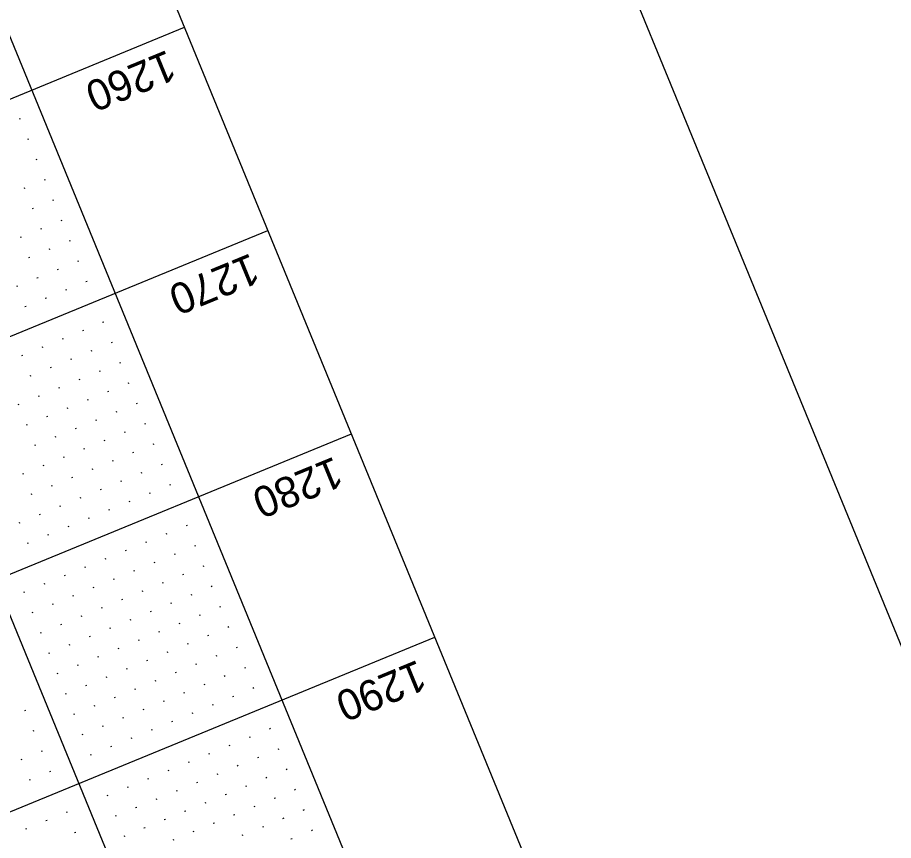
# Model space of a CAD drawing. Extents: x 2148770 to 2150891, y 142633 to 144465.
# Drawn here: x 2150307.4 to 2150506.7, y 143987.8 to 144175 of the extents above; entities that cross this region are included whole.
import ezdxf

# ---------------------------------------------------------------- set-up
doc = ezdxf.new("R2010")
doc.units = 0
for name, color, linetype in [('SHT_Plan_Profile_Sheet_Elev_Txt', 7, 'Continuous'), ('SHT_Plot_Shape_Half', 7, 'Continuous'), ('SHT_Profile_Grid_Major', 7, 'Continuous'), ('SHT_Profile_Grid_Minor', 7, 'Continuous'), ('SHT_Sheet_Border', 7, 'Continuous')]:
    doc.layers.add(name, color=color, linetype=linetype)

msp = doc.modelspace()

# ---------------------------------------------------------------- linework, layer by layer
at = {"layer": 'SHT_Plot_Shape_Half'}
msp.add_lwpolyline([(2150799.14, 143324.02), (2149226.52, 142678.36), (2148808.74, 143695.93), (2150381.36, 144341.59)], close=True, dxfattribs=at)
at = {"layer": 'SHT_Profile_Grid_Major'}
for p, q in [((2150226.36, 144232.01), (2150416.26, 143769.48)), ((2150345.29, 144172.74), (2148888.3, 143574.55)), ((2150364.28, 144126.48), (2148907.29, 143528.3)), ((2150383.27, 144080.23), (2148926.28, 143482.05)), ((2150402.26, 144033.98), (2148945.27, 143435.79))]:
    msp.add_line(p, q, dxfattribs=at)
at = {"layer": 'SHT_Profile_Grid_Minor'}
for p, q in [((2150307.98, 144152.02), (2150307.75, 144151.92)), ((2150309.88, 144147.39), (2150309.65, 144147.3)), ((2150311.78, 144142.77), (2150311.55, 144142.67)), ((2150313.68, 144138.14), (2150313.45, 144138.05)), ((2150309.06, 144136.24), (2150308.82, 144136.15)), ((2150315.58, 144133.52), (2150315.35, 144133.42)), ((2150310.96, 144131.62), (2150310.72, 144131.52)), ((2150317.48, 144128.89), (2150317.25, 144128.8)), ((2150312.85, 144126.99), (2150312.62, 144126.9)), ((2150308.23, 144125.09), (2150308, 144125)), ((2150319.38, 144124.27), (2150319.15, 144124.17)), ((2150314.75, 144122.37), (2150314.52, 144122.27)), ((2150310.13, 144120.47), (2150309.9, 144120.37)), ((2150321.28, 144119.64), (2150321.05, 144119.55)), ((2150316.65, 144117.74), (2150316.42, 144117.65)), ((2150312.03, 144115.84), (2150311.8, 144115.75)), ((2150323.18, 144115.02), (2150322.95, 144114.92)), ((2150307.4, 144113.94), (2150307.17, 144113.85)), ((2150318.55, 144113.12), (2150318.32, 144113.02)), ((2150313.93, 144111.22), (2150313.69, 144111.12)), ((2150309.3, 144109.32), (2150309.07, 144109.22)), ((2150326.97, 144105.77), (2150326.74, 144105.67)), ((2150322.35, 144103.87), (2150322.12, 144103.77)), ((2150317.72, 144101.97), (2150317.49, 144101.87)), ((2150328.87, 144101.14), (2150328.64, 144101.05)), ((2150313.1, 144100.07), (2150312.87, 144099.97)), ((2150324.25, 144099.24), (2150324.02, 144099.15)), ((2150308.47, 144098.17), (2150308.24, 144098.07)), ((2150319.62, 144097.34), (2150319.39, 144097.25)), ((2150315, 144095.44), (2150314.77, 144095.35)), ((2150330.77, 144096.51), (2150330.54, 144096.42)), ((2150310.37, 144093.54), (2150310.14, 144093.45)), ((2150326.15, 144094.62), (2150325.92, 144094.52)), ((2150321.52, 144092.72), (2150321.29, 144092.62)), ((2150332.67, 144091.89), (2150332.44, 144091.79)), ((2150316.9, 144090.82), (2150316.67, 144090.72)), ((2150328.05, 144089.99), (2150327.81, 144089.9)), ((2150307.65, 144087.02), (2150307.41, 144086.92)), ((2150312.27, 144088.92), (2150312.04, 144088.82)), ((2150323.42, 144088.09), (2150323.19, 144088)), ((2150334.57, 144087.26), (2150334.34, 144087.17)), ((2150318.8, 144086.19), (2150318.56, 144086.1)), ((2150329.95, 144085.37), (2150329.71, 144085.27)), ((2150314.17, 144084.29), (2150313.94, 144084.2)), ((2150325.32, 144083.47), (2150325.09, 144083.37)), ((2150309.54, 144082.39), (2150309.31, 144082.3)), ((2150320.69, 144081.57), (2150320.46, 144081.47)), ((2150336.47, 144082.64), (2150336.24, 144082.54)), ((2150316.07, 144079.67), (2150315.84, 144079.57)), ((2150331.84, 144080.74), (2150331.61, 144080.64)), ((2150311.44, 144077.77), (2150311.21, 144077.67)), ((2150327.22, 144078.84), (2150326.99, 144078.75)), ((2150338.37, 144078.01), (2150338.14, 144077.92)), ((2150317.97, 144075.04), (2150317.74, 144074.95)), ((2150322.59, 144076.94), (2150322.36, 144076.85)), ((2150333.74, 144076.11), (2150333.51, 144076.02)), ((2150313.34, 144073.14), (2150313.11, 144073.05)), ((2150329.12, 144074.22), (2150328.89, 144074.12)), ((2150340.27, 144073.39), (2150340.04, 144073.29)), ((2150308.72, 144071.24), (2150308.49, 144071.15)), ((2150324.49, 144072.32), (2150324.26, 144072.22)), ((2150335.64, 144071.49), (2150335.41, 144071.39)), ((2150319.87, 144070.42), (2150319.64, 144070.32)), ((2150331.02, 144069.59), (2150330.79, 144069.5)), ((2150315.24, 144068.52), (2150315.01, 144068.42)), ((2150326.39, 144067.69), (2150326.16, 144067.6)), ((2150342.17, 144068.76), (2150341.94, 144068.67)), ((2150310.62, 144066.62), (2150310.39, 144066.52)), ((2150321.77, 144065.79), (2150321.53, 144065.7)), ((2150337.54, 144066.86), (2150337.31, 144066.77)), ((2150317.14, 144063.89), (2150316.91, 144063.8)), ((2150328.29, 144063.07), (2150328.06, 144062.97)), ((2150332.92, 144064.96), (2150332.68, 144064.87)), ((2150312.52, 144061.99), (2150312.28, 144061.9)), ((2150323.67, 144061.17), (2150323.43, 144061.07)), ((2150307.89, 144060.1), (2150307.66, 144060)), ((2150319.04, 144059.27), (2150318.81, 144059.17)), ((2150345.96, 144059.51), (2150345.73, 144059.42)), ((2150314.41, 144057.37), (2150314.18, 144057.27)), ((2150341.34, 144057.61), (2150341.11, 144057.52)), ((2150309.79, 144055.47), (2150309.56, 144055.37)), ((2150336.71, 144055.71), (2150336.48, 144055.62)), ((2150332.09, 144053.82), (2150331.86, 144053.72)), ((2150347.86, 144054.89), (2150347.63, 144054.79)), ((2150327.46, 144051.92), (2150327.23, 144051.82)), ((2150338.61, 144051.09), (2150338.38, 144050.99)), ((2150343.24, 144052.99), (2150343.01, 144052.89)), ((2150322.84, 144050.02), (2150322.61, 144049.92)), ((2150333.99, 144049.19), (2150333.76, 144049.09)), ((2150349.76, 144050.26), (2150349.53, 144050.17)), ((2150318.21, 144048.12), (2150317.98, 144048.02)), ((2150329.36, 144047.29), (2150329.13, 144047.2)), ((2150345.14, 144048.36), (2150344.91, 144048.27)), ((2150313.59, 144046.22), (2150313.36, 144046.12)), ((2150324.74, 144045.39), (2150324.51, 144045.3)), ((2150340.51, 144046.46), (2150340.28, 144046.37)), ((2150351.66, 144045.64), (2150351.43, 144045.54)), ((2150308.96, 144044.32), (2150308.73, 144044.23)), ((2150320.11, 144043.49), (2150319.88, 144043.4)), ((2150335.89, 144044.56), (2150335.66, 144044.47)), ((2150347.04, 144043.74), (2150346.8, 144043.64)), ((2150315.49, 144041.59), (2150315.25, 144041.5)), ((2150331.26, 144042.67), (2150331.03, 144042.57)), ((2150342.41, 144041.84), (2150342.18, 144041.74)), ((2150310.86, 144039.69), (2150310.63, 144039.6)), ((2150326.64, 144040.77), (2150326.4, 144040.67)), ((2150337.79, 144039.94), (2150337.55, 144039.84)), ((2150353.56, 144041.01), (2150353.33, 144040.92)), ((2150322.01, 144038.87), (2150321.78, 144038.77)), ((2150333.16, 144038.04), (2150332.93, 144037.95)), ((2150344.31, 144037.21), (2150344.08, 144037.12)), ((2150348.94, 144039.11), (2150348.7, 144039.02)), ((2150317.39, 144036.97), (2150317.15, 144036.87)), ((2150328.53, 144036.14), (2150328.3, 144036.05)), ((2150339.68, 144035.31), (2150339.45, 144035.22)), ((2150355.46, 144036.39), (2150355.23, 144036.29)), ((2150312.76, 144035.07), (2150312.53, 144034.97)), ((2150323.91, 144034.24), (2150323.68, 144034.15)), ((2150335.06, 144033.41), (2150334.83, 144033.32)), ((2150350.83, 144034.49), (2150350.6, 144034.39)), ((2150319.28, 144032.34), (2150319.05, 144032.25)), ((2150330.43, 144031.52), (2150330.2, 144031.42)), ((2150346.21, 144032.59), (2150345.98, 144032.49)), ((2150357.36, 144031.76), (2150357.13, 144031.67)), ((2150314.66, 144030.44), (2150314.43, 144030.35)), ((2150325.81, 144029.62), (2150325.58, 144029.52)), ((2150341.58, 144030.69), (2150341.35, 144030.59)), ((2150352.73, 144029.86), (2150352.5, 144029.77)), ((2150321.18, 144027.72), (2150320.95, 144027.62)), ((2150336.96, 144028.79), (2150336.73, 144028.69)), ((2150348.11, 144027.96), (2150347.88, 144027.87)), ((2150316.56, 144025.82), (2150316.33, 144025.72)), ((2150332.33, 144026.89), (2150332.1, 144026.8)), ((2150343.48, 144026.06), (2150343.25, 144025.97)), ((2150354.63, 144025.24), (2150354.4, 144025.14)), ((2150359.26, 144027.13), (2150359.03, 144027.04)), ((2150327.71, 144024.99), (2150327.48, 144024.9)), ((2150338.86, 144024.16), (2150338.63, 144024.07)), ((2150350.01, 144023.34), (2150349.78, 144023.24)), ((2150318.46, 144021.19), (2150318.23, 144021.1)), ((2150323.08, 144023.09), (2150322.85, 144023)), ((2150334.23, 144022.27), (2150334, 144022.17)), ((2150345.38, 144021.44), (2150345.15, 144021.34)), ((2150361.16, 144022.51), (2150360.93, 144022.41)), ((2150329.61, 144020.37), (2150329.38, 144020.27)), ((2150340.76, 144019.54), (2150340.52, 144019.44)), ((2150356.53, 144020.61), (2150356.3, 144020.52)), ((2150309.21, 144017.4), (2150308.97, 144017.3)), ((2150324.98, 144018.47), (2150324.75, 144018.37)), ((2150336.13, 144017.64), (2150335.9, 144017.54)), ((2150351.91, 144018.71), (2150351.67, 144018.62)), ((2150320.36, 144016.57), (2150320.12, 144016.47)), ((2150331.51, 144015.74), (2150331.27, 144015.65)), ((2150347.28, 144016.81), (2150347.05, 144016.72)), ((2150326.88, 144013.84), (2150326.65, 144013.75)), ((2150342.66, 144014.91), (2150342.42, 144014.82)), ((2150364.95, 144013.26), (2150364.72, 144013.16)), ((2150311.11, 144012.77), (2150310.87, 144012.68)), ((2150322.25, 144011.94), (2150322.02, 144011.85)), ((2150338.03, 144013.01), (2150337.8, 144012.92)), ((2150360.33, 144011.36), (2150360.1, 144011.26)), ((2150333.4, 144011.12), (2150333.17, 144011.02)), ((2150355.7, 144009.46), (2150355.47, 144009.37)), ((2150313, 144008.14), (2150312.77, 144008.05)), ((2150324.15, 144007.32), (2150323.92, 144007.22)), ((2150328.78, 144009.22), (2150328.55, 144009.12)), ((2150351.08, 144007.56), (2150350.85, 144007.47)), ((2150366.85, 144008.63), (2150366.62, 144008.54)), ((2150308.38, 144006.25), (2150308.15, 144006.15)), ((2150346.45, 144005.66), (2150346.22, 144005.57)), ((2150362.23, 144006.73), (2150362, 144006.64)), ((2150314.9, 144003.52), (2150314.67, 144003.42)), ((2150341.83, 144003.76), (2150341.6, 144003.67)), ((2150357.6, 144004.84), (2150357.37, 144004.74)), ((2150368.75, 144004.01), (2150368.52, 144003.91)), ((2150310.28, 144001.62), (2150310.05, 144001.53)), ((2150337.2, 144001.86), (2150336.97, 144001.77)), ((2150352.98, 144002.94), (2150352.75, 144002.84)), ((2150364.13, 144002.11), (2150363.9, 144002.01)), ((2150332.58, 143999.97), (2150332.35, 143999.87)), ((2150348.35, 144001.04), (2150348.12, 144000.94)), ((2150359.5, 144000.21), (2150359.27, 144000.12)), ((2150370.65, 143999.38), (2150370.42, 143999.29)), ((2150327.95, 143998.07), (2150327.72, 143997.97)), ((2150343.73, 143999.14), (2150343.5, 143999.04)), ((2150354.88, 143998.31), (2150354.65, 143998.22)), ((2150366.03, 143997.48), (2150365.79, 143997.39)), ((2150334.48, 143995.34), (2150334.24, 143995.25)), ((2150339.1, 143997.24), (2150338.87, 143997.14)), ((2150350.25, 143996.41), (2150350.02, 143996.32)), ((2150361.4, 143995.58), (2150361.17, 143995.49)), ((2150318.7, 143994.27), (2150318.47, 143994.17)), ((2150329.85, 143993.44), (2150329.62, 143993.35)), ((2150345.63, 143994.51), (2150345.39, 143994.42)), ((2150356.78, 143993.69), (2150356.54, 143993.59)), ((2150372.55, 143994.76), (2150372.32, 143994.66)), ((2150314.08, 143992.37), (2150313.84, 143992.27)), ((2150341, 143992.61), (2150340.77, 143992.52)), ((2150352.15, 143991.79), (2150351.92, 143991.69)), ((2150367.93, 143992.86), (2150367.69, 143992.76)), ((2150309.45, 143990.47), (2150309.22, 143990.38)), ((2150320.6, 143989.64), (2150320.37, 143989.55)), ((2150336.38, 143990.72), (2150336.14, 143990.62)), ((2150347.52, 143989.89), (2150347.29, 143989.79)), ((2150363.3, 143990.96), (2150363.07, 143990.86)), ((2150374.45, 143990.13), (2150374.22, 143990.04)), ((2150331.75, 143988.82), (2150331.52, 143988.72)), ((2150342.9, 143987.99), (2150342.67, 143987.89)), ((2150358.67, 143989.06), (2150358.44, 143988.97)), ((2150369.82, 143988.23), (2150369.59, 143988.14))]:
    msp.add_line(p, q, dxfattribs=at)
at = {"layer": 'SHT_Sheet_Border'}
msp.add_line((2150272.62, 144251), (2150462.52, 143788.47), dxfattribs=at)
msp.add_lwpolyline([(2150699.45, 143310.11), (2149242.47, 142711.93), (2148843.68, 143683.25), (2150300.66, 144281.43)], close=True, dxfattribs=at)

# ---------------------------------------------------------------- texts
at = {"layer": 'SHT_Plan_Profile_Sheet_Elev_Txt'}
for s, p in [('1260', (2150341.49, 144167.77)), ('1270', (2150360.48, 144121.52)), ('1280', (2150379.47, 144075.26)), ('1290', (2150398.46, 144029.01))]:
    msp.add_text(s, height=7, rotation=202.3213, dxfattribs=at).set_placement(p)

doc.saveas('drawing.dxf')
